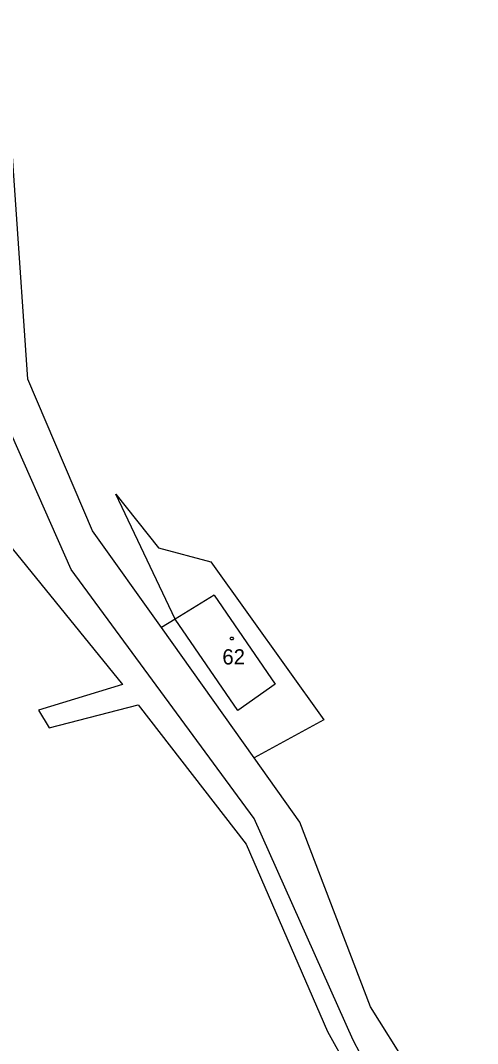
# Model space of a CAD drawing. Extents: x -799786 to -795190, y -1021716 to -1017834.
# Drawn here: x -797657.9 to -797606.8, y -1019260.7 to -1019146 of the extents above; entities that cross this region are included whole.
import ezdxf

# ---------------------------------------------------------------- set-up
doc = ezdxf.new("R2010")
doc.units = 0
for name, color, linetype in [('Default', 7, 'Continuous'), ('KN_HRANICE', 7, 'Continuous'), ('KN_KULTURY', 7, 'Continuous'), ('KN_PARCELY', 7, 'Continuous'), ('KN_SLUCKY', 7, 'Continuous')]:
    doc.layers.add(name, color=color, linetype=linetype)

# ---------------------------------------------------------------- blocks, each defined once
blk = doc.blocks.new('NAHRADNI_SYMBOL')
at = {"layer": 'Default'}
blk.add_lwpolyline([(0.09, 0.15), (0.18, 0), (0.09, -0.15), (-0.09, -0.15), (-0.18, 0), (-0.09, 0.15), (0.09, 0.15)], dxfattribs=at)

msp = doc.modelspace()

# ---------------------------------------------------------------- linework, layer by layer
at = {"layer": 'KN_HRANICE'}
for p, q in [((-797657.11, -1019186.19), (-797659.88, -1019146)), ((-797649.89, -1019203.19), (-797657.11, -1019186.19)), ((-797652.26, -1019207.55), (-797660.98, -1019187.84)), ((-797668.59, -1019193.31), (-797646.53, -1019220.44)), ((-797640.62, -1019213.11), (-797647.28, -1019199.08)), ((-797647.28, -1019199.08), (-797642.5, -1019205.11)), ((-797642.16, -1019214.05), (-797649.89, -1019203.19)), ((-797642.5, -1019205.11), (-797636.63, -1019206.67)), ((-797631.78, -1019235.45), (-797652.26, -1019207.55)), ((-797636.63, -1019206.67), (-797623.95, -1019224.37)), ((-797640.62, -1019213.11), (-797642.16, -1019214.05)), ((-797631.76, -1019228.65), (-797642.16, -1019214.05)), ((-797646.53, -1019220.44), (-797655.93, -1019223.31)), ((-797655.93, -1019223.31), (-797654.75, -1019225.3)), ((-797654.75, -1019225.3), (-797644.75, -1019222.72)), ((-797644.75, -1019222.72), (-797632.67, -1019238.34)), ((-797623.95, -1019224.37), (-797631.76, -1019228.65)), ((-797626.64, -1019235.84), (-797631.76, -1019228.65)), ((-797620.69, -1019260.31), (-797631.78, -1019235.45)), ((-797618.72, -1019256.54), (-797626.64, -1019235.84)), ((-797632.67, -1019238.34), (-797623.57, -1019259.32)), ((-797606.75, -1019275.62), (-797618.72, -1019256.54)), ((-797623.57, -1019259.32), (-797614.12, -1019276.14)), ((-797612.84, -1019275.07), (-797620.69, -1019260.31))]:
    msp.add_line(p, q, dxfattribs=at)
at = {"layer": 'KN_SLUCKY'}
for p, q in [((-797636.24, -1019210.43), (-797640.62, -1019213.11)), ((-797636.24, -1019210.43), (-797629.43, -1019220.38)), ((-797633.58, -1019223.35), (-797640.62, -1019213.11)), ((-797629.43, -1019220.38), (-797633.58, -1019223.35))]:
    msp.add_line(p, q, dxfattribs=at)

# ---------------------------------------------------------------- block references
at = {"layer": 'KN_KULTURY'}
msp.add_blockref('NAHRADNI_SYMBOL', (-797634.28, -1019215.29), dxfattribs=at)

# ---------------------------------------------------------------- texts
at = {"layer": 'KN_PARCELY'}
msp.add_text('62', height=1.7, dxfattribs=at).set_placement((-797635.33, -1019218.18))

doc.saveas('drawing.dxf')
